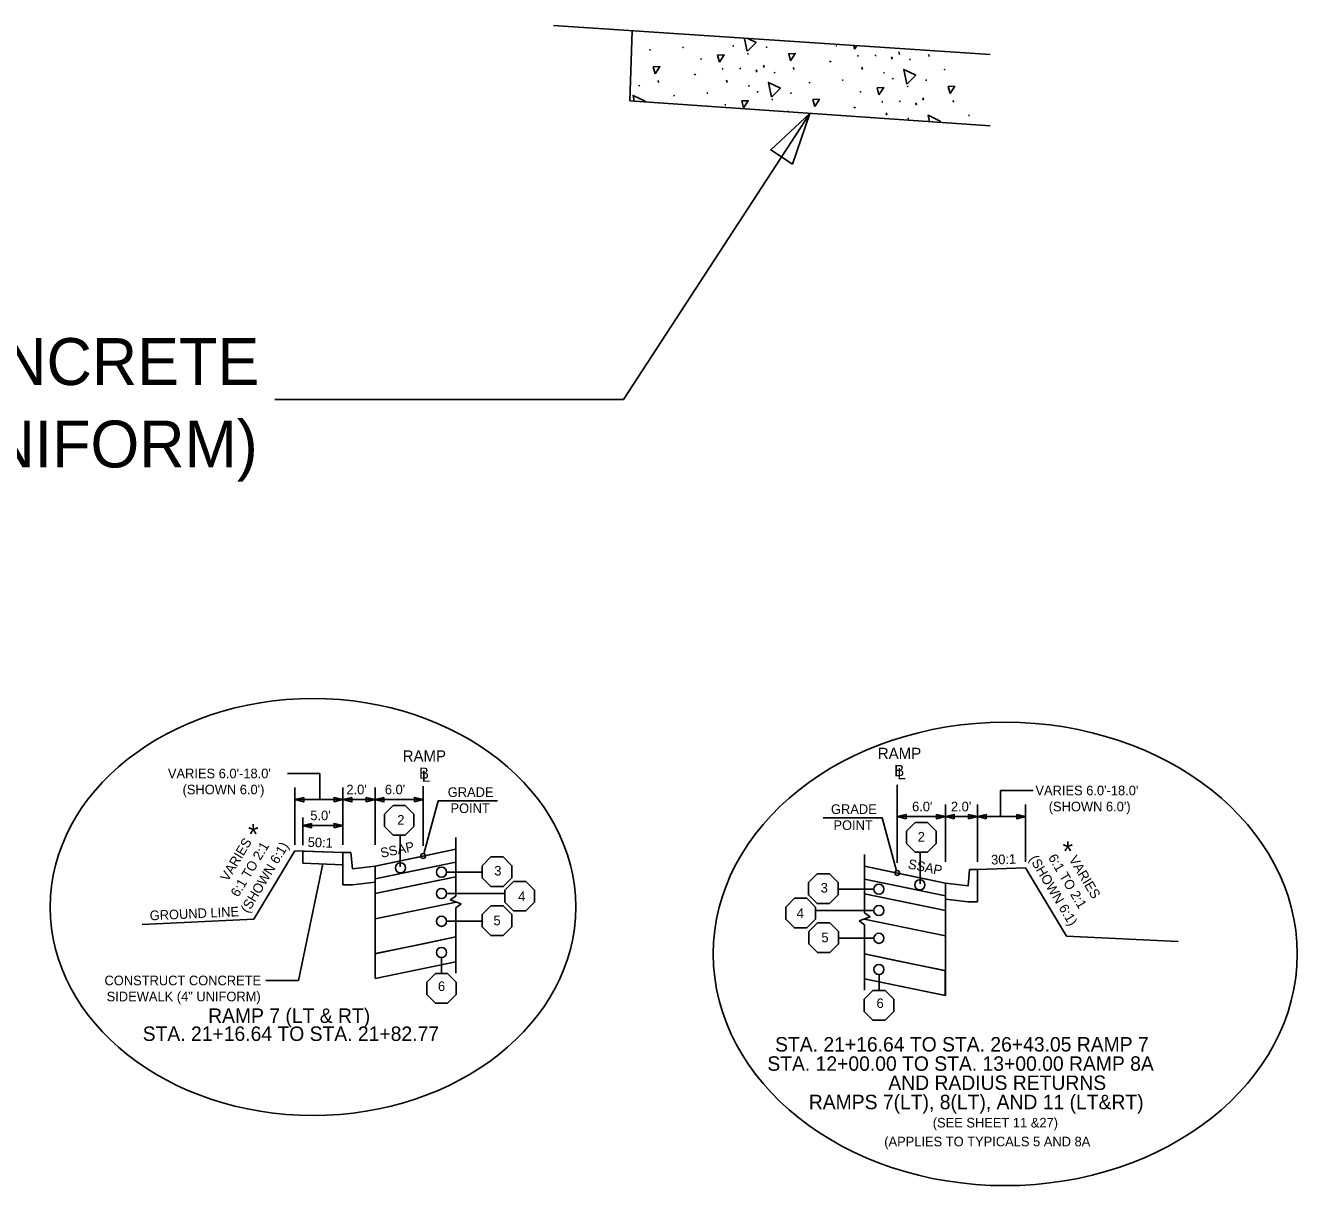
# Model space of a CAD drawing. Extents: x 4932 to 5887, y 4809 to 5473.
# Drawn here: x 5216 to 5374.1, y 5328.4 to 5473 of the extents above; entities that cross this region are included whole.
import ezdxf

# ---------------------------------------------------------------- set-up
doc = ezdxf.new("R2010")
doc.units = 0
for name, color, linetype in [('Level 1', 7, 'Continuous'), ('Level 16', 7, 'Continuous'), ('Level 25', 7, 'Continuous'), ('RD_QTY_Intermediate', 7, 'Continuous'), ('RD_QTY_Sub_Base', 7, 'Continuous'), ('RD_QTY_Surf_Course', 7, 'Continuous'), ('RD_SHT_Typical', 7, 'Continuous'), ('RD_TX_TypSect', 7, 'Continuous'), ('RD_XS_CurbBase', 7, 'Continuous'), ('RD_XS_CurbFront', 7, 'Continuous'), ('RD_XS_CurbTop', 7, 'Continuous'), ('RD_XS_EarthShd', 7, 'Continuous'), ('RD_XS_ExGround', 7, 'Continuous'), ('typical_on', 7, 'Continuous')]:
    doc.layers.add(name, color=color, linetype=linetype)

msp = doc.modelspace()

# ---------------------------------------------------------------- linework, layer by layer
at = {"layer": 'Level 1'}
for p, q in [((5291.36, 5463.6), (5291.67, 5472.36)), ((5336.27, 5460.47), (5291.36, 5463.59)), ((5290.56, 5426.39), (5313.81, 5462.03)), ((5247.12, 5426.39), (5290.56, 5426.39))]:
    msp.add_line(p, q, dxfattribs=at)
msp.add_lwpolyline([(5311.63, 5455.72), (5313.81, 5462.03), (5308.92, 5457.49)], close=True, dxfattribs=at)
at = {"layer": 'Level 16'}
for p, q in [((5324.06, 5468.78), (5323.98, 5469.09)), ((5324.96, 5469.39), (5324.87, 5469.7)), ((5328.68, 5469.15), (5328.62, 5469.37)), ((5308.09, 5467.77), (5308.01, 5468.07)), ((5311.82, 5467.53), (5311.75, 5467.74)), ((5316.24, 5468.53), (5316.46, 5468.46)), ((5320.35, 5467.51), (5320.27, 5467.81)), ((5294.95, 5465.9), (5294.89, 5466.12)), ((5299.37, 5466.91), (5299.6, 5466.83)), ((5303.48, 5465.89), (5303.4, 5466.19)), ((5307.2, 5467.16), (5307.12, 5467.46)), ((5319.27, 5462.82), (5319.49, 5462.74)), ((5327.09, 5463.07), (5327.01, 5463.37)), ((5327.98, 5463.68), (5327.9, 5463.99)), ((5331.71, 5463.44), (5331.65, 5463.65)), ((5311.08, 5462.22), (5311.04, 5462.36)), ((5314.8, 5461.96), (5314.78, 5462.03)), ((5323.38, 5461.8), (5323.29, 5462.1))]:
    msp.add_line(p, q, dxfattribs=at)
for points in [[(5305.99, 5469.78), (5305.66, 5471.34)], [(5306.09, 5471.37), (5307.1, 5470.88), (5306.02, 5469.8)], [(5293.86, 5469.91), (5293.83, 5469.96), (5293.92, 5469.95)], [(5298.01, 5470.23), (5297.98, 5470.28), (5298.07, 5470.27)], [(5302.52, 5468.43), (5302.3, 5469.3), (5303.1, 5469.34), (5302.52, 5468.43)], [(5304.25, 5470.41), (5304.22, 5470.46), (5304.32, 5470.44)], [(5306.09, 5469.43), (5306.06, 5469.48), (5306.16, 5469.47)], [(5308.41, 5470.24), (5308.38, 5470.29), (5308.48, 5470.28)], [(5311.38, 5468.61), (5311.16, 5469.48), (5311.97, 5469.52), (5311.38, 5468.61)], [(5317.11, 5470.4), (5317.08, 5470.44), (5317.18, 5470.43)], [(5319.38, 5470.05), (5319.27, 5470.5)], [(5319.61, 5470.41), (5319.38, 5470.05)], [(5319.78, 5469.16), (5319.75, 5469.21), (5319.85, 5469.2)], [(5321.98, 5469.22), (5321.95, 5469.26), (5322.05, 5469.25)], [(5291.54, 5468.67), (5291.62, 5468.66)], [(5291.55, 5468.62), (5291.54, 5468.63)], [(5294.52, 5466.99), (5294.29, 5467.86), (5295.1, 5467.9), (5294.52, 5466.99)], [(5300.24, 5468.77), (5300.21, 5468.82), (5300.31, 5468.81)], [(5302.92, 5467.54), (5302.89, 5467.59), (5302.98, 5467.58)], [(5305.12, 5467.59), (5305.09, 5467.64), (5305.19, 5467.63)], [(5325.89, 5465.69), (5325.5, 5467.52), (5327, 5466.79), (5325.91, 5465.72)], [(5326.26, 5468.7), (5326.23, 5468.75), (5326.33, 5468.74)], [(5330.61, 5467.45), (5330.58, 5467.5), (5330.68, 5467.49)], [(5309.4, 5467.08), (5309.37, 5467.12), (5309.46, 5467.11)], [(5317.9, 5466.14), (5317.87, 5466.19), (5317.97, 5466.18)], [(5323.05, 5467.06), (5323.02, 5467.11), (5323.12, 5467.1)], [(5324.14, 5466.32), (5324.11, 5466.37), (5324.21, 5466.36)], [(5328.3, 5466.16), (5328.27, 5466.2), (5328.37, 5466.19)], [(5292.53, 5465.45), (5292.5, 5465.5), (5292.6, 5465.49)], [(5301.03, 5464.52), (5301, 5464.57), (5301.1, 5464.56)], [(5306.19, 5465.44), (5306.16, 5465.49), (5306.26, 5465.47)], [(5307.28, 5464.7), (5307.25, 5464.74), (5307.35, 5464.73)], [(5309.02, 5464.07), (5308.63, 5465.9), (5310.13, 5465.17), (5309.05, 5464.09)], [(5311.44, 5464.53), (5311.41, 5464.58), (5311.51, 5464.57)], [(5313.75, 5465.83), (5313.72, 5465.87), (5313.82, 5465.86)], [(5320.13, 5464.68), (5320.1, 5464.73), (5320.2, 5464.72)], [(5322.41, 5464.34), (5322.19, 5465.21), (5323, 5465.25), (5322.41, 5464.34)], [(5325.98, 5465.34), (5325.95, 5465.39), (5326.05, 5465.38)], [(5331.28, 5464.52), (5331.05, 5465.39), (5331.86, 5465.43), (5331.28, 5464.52)], [(5291.92, 5463.55), (5291.77, 5464.27), (5293.27, 5463.55), (5293.19, 5463.46)], [(5296.88, 5464.2), (5296.85, 5464.25), (5296.95, 5464.24)], [(5303.27, 5463.06), (5303.24, 5463.11), (5303.34, 5463.1)], [(5305.54, 5462.72), (5305.33, 5463.59), (5306.13, 5463.62), (5305.54, 5462.72)], [(5309.12, 5463.72), (5309.09, 5463.77), (5309.19, 5463.76)], [(5314.41, 5462.9), (5314.18, 5463.77), (5314.99, 5463.81), (5314.41, 5462.9)], [(5322.81, 5463.45), (5322.78, 5463.5), (5322.88, 5463.49)], [(5325.01, 5463.5), (5324.98, 5463.55), (5325.08, 5463.54)], [(5326.08, 5461.35), (5326.05, 5461.4), (5326.15, 5461.39)], [(5328.7, 5461), (5328.53, 5461.81), (5330.03, 5461.08), (5329.86, 5460.92)], [(5333.64, 5461.74), (5333.61, 5461.79), (5333.71, 5461.78)]]:
    msp.add_lwpolyline(points, dxfattribs=at)
at = {"layer": 'Level 25'}
for p, q in [((5269.67, 5370.31), (5259.61, 5368.22)), ((5269.67, 5368.72), (5259.61, 5366.62)), ((5320.63, 5368.2), (5330.69, 5366.1)), ((5269.67, 5366.89), (5259.61, 5364.8)), ((5320.63, 5366.6), (5330.69, 5364.51)), ((5320.63, 5364.77), (5330.69, 5362.68))]:
    msp.add_line(p, q, dxfattribs=at)
for points in [[(5274.86, 5376.34), (5267.49, 5376.34), (5265.69, 5369.76)], [(5315.44, 5374.22), (5322.8, 5374.22), (5324.61, 5367.64)]]:
    msp.add_lwpolyline(points, dxfattribs=at)
at = {"layer": 'RD_QTY_Intermediate'}
for p, q in [((5265.61, 5367.87), (5269.67, 5368.72)), ((5269.67, 5368.72), (5269.67, 5366.89)), ((5259.61, 5366.62), (5265.61, 5367.87)), ((5259.61, 5365.36), (5259.61, 5366.62)), ((5259.61, 5364.8), (5259.61, 5366.46)), ((5259.61, 5366.46), (5259.61, 5365.36)), ((5269.67, 5366.89), (5265.61, 5366.05)), ((5320.63, 5366.6), (5320.63, 5364.77)), ((5324.69, 5365.75), (5320.63, 5366.6)), ((5265.61, 5366.05), (5259.61, 5364.8)), ((5320.63, 5364.77), (5324.69, 5363.93)), ((5330.69, 5364.51), (5324.69, 5365.75)), ((5324.69, 5363.93), (5330.69, 5362.68)), ((5330.69, 5363.24), (5330.69, 5364.51)), ((5330.69, 5362.68), (5330.69, 5364.34)), ((5330.69, 5364.34), (5330.69, 5363.24))]:
    msp.add_line(p, q, dxfattribs=at)
at = {"layer": 'RD_QTY_Sub_Base'}
for p, q in [((5259.63, 5357.3), (5265.63, 5358.54)), ((5265.63, 5358.54), (5269.67, 5359.38)), ((5269.67, 5359.38), (5269.67, 5356.28)), ((5259.63, 5354.2), (5259.63, 5357.3)), ((5320.63, 5357.26), (5320.63, 5354.16)), ((5324.66, 5356.42), (5320.63, 5357.26)), ((5269.67, 5356.28), (5259.63, 5354.2)), ((5330.67, 5355.18), (5324.66, 5356.42)), ((5320.63, 5354.16), (5330.66, 5352.09)), ((5330.66, 5352.09), (5330.67, 5355.18))]:
    msp.add_line(p, q, dxfattribs=at)
at = {"layer": 'RD_QTY_Surf_Course'}
for p, q in [((5265.61, 5369.47), (5269.67, 5370.31)), ((5269.67, 5370.31), (5269.67, 5368.72)), ((5259.61, 5368.22), (5265.61, 5369.47)), ((5259.61, 5366.62), (5259.61, 5368.22)), ((5269.67, 5368.72), (5265.61, 5367.87)), ((5324.69, 5367.35), (5320.63, 5368.2)), ((5320.63, 5368.2), (5320.63, 5366.6)), ((5265.61, 5367.87), (5259.61, 5366.62)), ((5320.63, 5366.6), (5324.69, 5365.75)), ((5330.69, 5366.1), (5324.69, 5367.35)), ((5324.69, 5365.75), (5330.69, 5364.51)), ((5330.69, 5364.51), (5330.69, 5366.1))]:
    msp.add_line(p, q, dxfattribs=at)
at = {"layer": 'RD_SHT_Typical'}
for p, q in [((5269.67, 5371.76), (5269.67, 5364.48)), ((5249.62, 5370.1), (5244.51, 5361.58)), ((5255.61, 5369.89), (5249.62, 5370.1)), ((5250.61, 5370.07), (5250.61, 5368.58)), ((5250.61, 5368.58), (5250.61, 5370.07)), ((5250.61, 5370.07), (5255.61, 5369.89)), ((5250.61, 5370.07), (5255.61, 5369.89)), ((5255.61, 5369.89), (5250.61, 5370.07)), ((5255.61, 5369.89), (5255.61, 5368.39)), ((5320.63, 5369.64), (5320.63, 5362.37)), ((5255.61, 5368.39), (5250.61, 5368.58)), ((5255.61, 5368.39), (5250.61, 5368.58)), ((5259.61, 5368.22), (5265.61, 5369.47)), ((5259.61, 5368.22), (5259.61, 5354.19)), ((5334.69, 5367.77), (5340.68, 5367.98)), ((5340.68, 5367.98), (5345.79, 5359.47)), ((5259.61, 5366.62), (5265.63, 5367.86)), ((5330.69, 5366.1), (5324.69, 5367.35)), ((5259.61, 5364.8), (5265.61, 5366.05)), ((5259.61, 5364.8), (5259.61, 5362.54)), ((5330.69, 5364.51), (5324.66, 5365.75)), ((5330.69, 5366.1), (5330.69, 5352.07)), ((5330.69, 5362.68), (5324.69, 5363.93)), ((5269.67, 5363.01), (5269.67, 5354.85)), ((5330.69, 5362.68), (5330.69, 5360.43)), ((5320.63, 5360.89), (5320.63, 5352.73))]:
    msp.add_line(p, q, dxfattribs=at)
for points in [[(5269.67, 5370.31), (5265.61, 5369.47)], [(5269.67, 5368.72), (5265.61, 5367.87)], [(5320.63, 5368.2), (5324.69, 5367.35)], [(5269.67, 5366.89), (5265.61, 5366.05)], [(5320.63, 5366.6), (5324.69, 5365.75)], [(5320.63, 5364.77), (5324.69, 5363.93)], [(5269.72, 5363.72), (5259.61, 5361.62)], [(5320.58, 5361.6), (5330.69, 5359.5)], [(5269.67, 5359.38), (5259.61, 5357.29)], [(5320.63, 5357.26), (5330.69, 5355.17)], [(5269.67, 5356.28), (5259.61, 5354.19)], [(5320.63, 5354.16), (5330.69, 5352.07)]]:
    msp.add_lwpolyline(points, dxfattribs=at)
at = {"layer": 'RD_TX_TypSect'}
for p, q in [((5248.68, 5379.77), (5252.71, 5379.77)), ((5252.71, 5379.77), (5252.71, 5376.51)), ((5249.62, 5370.87), (5249.62, 5378.03)), ((5255.61, 5370.87), (5255.61, 5378.03)), ((5259.61, 5370.87), (5259.61, 5378.03)), ((5265.61, 5378.16), (5265.61, 5370.72)), ((5324.69, 5378.33), (5324.69, 5368.6)), ((5341.62, 5377.65), (5337.58, 5377.65)), ((5337.58, 5377.65), (5337.58, 5374.39)), ((5255.61, 5376.5), (5249.62, 5376.5)), ((5259.61, 5376.5), (5255.61, 5376.5)), ((5265.61, 5376.5), (5259.61, 5376.5)), ((5330.69, 5368.75), (5330.69, 5375.91)), ((5334.68, 5368.75), (5334.68, 5375.91)), ((5340.68, 5368.75), (5340.68, 5375.91)), ((5250.61, 5370.83), (5250.61, 5374.26)), ((5324.69, 5374.38), (5330.69, 5374.38)), ((5330.69, 5374.38), (5334.68, 5374.38)), ((5334.68, 5374.38), (5340.68, 5374.38)), ((5255.61, 5373.27), (5250.61, 5373.27)), ((5262.73, 5368.12), (5262.73, 5372.07)), ((5327.56, 5366), (5327.56, 5369.95)), ((5250.05, 5353.97), (5253.11, 5368.48)), ((5268.52, 5367.46), (5272.93, 5367.46)), ((5268.52, 5364.8), (5275.8, 5364.8)), ((5321.78, 5365.34), (5317.37, 5365.34)), ((5269.67, 5364.48), (5268.98, 5364)), ((5270.34, 5363.49), (5268.98, 5364)), ((5270.34, 5363.49), (5269.67, 5363.01)), ((5321.78, 5362.68), (5314.49, 5362.68)), ((5319.95, 5361.37), (5321.31, 5361.88)), ((5320.63, 5362.37), (5321.31, 5361.88)), ((5268.52, 5361.33), (5272.93, 5361.33)), ((5319.95, 5361.37), (5320.63, 5360.89)), ((5321.78, 5359.21), (5317.37, 5359.21)), ((5267.88, 5354.82), (5267.88, 5356.82)), ((5246.01, 5353.97), (5250.05, 5353.97)), ((5322.42, 5352.7), (5322.42, 5354.7))]:
    msp.add_line(p, q, dxfattribs=at)
for points in [[(5250.72, 5376.77), (5250.72, 5376.22), (5249.62, 5376.5)], [(5254.51, 5376.22), (5254.51, 5376.77), (5255.61, 5376.5)], [(5256.72, 5376.77), (5256.72, 5376.22), (5255.61, 5376.5)], [(5258.51, 5376.22), (5258.51, 5376.77), (5259.61, 5376.5)], [(5260.71, 5376.77), (5260.71, 5376.22), (5259.61, 5376.5)], [(5264.51, 5376.22), (5264.51, 5376.77), (5265.61, 5376.5)], [(5325.79, 5374.11), (5325.79, 5374.65), (5324.69, 5374.38)], [(5329.58, 5374.65), (5329.58, 5374.11), (5330.69, 5374.38)], [(5331.79, 5374.11), (5331.79, 5374.65), (5330.69, 5374.38)], [(5333.58, 5374.65), (5333.58, 5374.11), (5334.68, 5374.38)], [(5335.79, 5374.11), (5335.79, 5374.65), (5334.68, 5374.38)], [(5339.58, 5374.65), (5339.58, 5374.11), (5340.68, 5374.38)], [(5251.71, 5373.54), (5251.71, 5372.99), (5250.61, 5373.27)], [(5254.51, 5372.99), (5254.51, 5373.54), (5255.61, 5373.27)]]:
    msp.add_lwpolyline(points, close=True, dxfattribs=at)
for centre, radius in [((5265.61, 5369.47), 0.3), ((5262.79, 5368), 0.63), ((5267.89, 5367.46), 0.63), ((5324.69, 5367.35), 0.3), ((5327.51, 5365.88), 0.63), ((5267.89, 5364.8), 0.63), ((5322.41, 5365.34), 0.63), ((5322.41, 5362.68), 0.63), ((5267.89, 5361.33), 0.63), ((5322.41, 5359.21), 0.63), ((5267.89, 5357.45), 0.63), ((5322.41, 5355.33), 0.63)]:
    msp.add_circle(centre, radius, dxfattribs=at)
for centre, major_axis in [((5251.88, 5363.11), (-32.75, 0)), ((5338.15, 5357.26), (-36.39, 0))]:
    msp.add_ellipse(centre, major_axis=major_axis, ratio=0.793631, dxfattribs=at)
at = {"layer": 'RD_XS_CurbBase'}
for p, q in [((5255.61, 5369.89), (5255.61, 5365.89)), ((5334.69, 5367.77), (5334.69, 5363.77)), ((5255.61, 5365.89), (5256.78, 5365.89)), ((5256.78, 5365.89), (5259.61, 5366.22)), ((5333.52, 5363.77), (5330.69, 5364.1)), ((5334.69, 5363.77), (5333.52, 5363.77))]:
    msp.add_line(p, q, dxfattribs=at)
at = {"layer": 'RD_XS_CurbFront'}
for p, q in [((5259.61, 5368.22), (5259.61, 5366.72)), ((5330.69, 5366.1), (5330.69, 5364.6))]:
    msp.add_line(p, q, dxfattribs=at)
at = {"layer": 'RD_XS_CurbTop'}
for p, q in [((5256.61, 5369.89), (5255.61, 5369.89)), ((5256.78, 5367.89), (5256.61, 5369.89)), ((5259.61, 5368.22), (5256.78, 5367.89)), ((5333.52, 5365.77), (5333.69, 5367.77)), ((5333.69, 5367.77), (5334.69, 5367.77)), ((5330.69, 5366.1), (5333.52, 5365.77))]:
    msp.add_line(p, q, dxfattribs=at)
at = {"layer": 'RD_XS_EarthShd'}
msp.add_line((5336.27, 5469.38), (5281.86, 5473.01), dxfattribs=at)
at = {"layer": 'RD_XS_ExGround'}
for p, q in [((5230.59, 5360.95), (5244.51, 5361.58)), ((5345.79, 5359.47), (5359.71, 5358.83))]:
    msp.add_line(p, q, dxfattribs=at)
at = {"layer": 'typical_on'}
for points in [[(5260.77, 5374.68), (5260.77, 5373.15), (5261.85, 5372.07), (5263.38, 5372.07), (5264.46, 5373.15), (5264.46, 5374.68), (5263.38, 5375.76), (5261.85, 5375.76)], [(5329.53, 5372.56), (5329.53, 5371.03), (5328.45, 5369.95), (5326.92, 5369.95), (5325.84, 5371.03), (5325.84, 5372.56), (5326.92, 5373.64), (5328.45, 5373.64)], [(5272.98, 5368.26), (5272.98, 5366.73), (5274.06, 5365.65), (5275.59, 5365.65), (5276.67, 5366.73), (5276.67, 5368.26), (5275.59, 5369.35), (5274.06, 5369.35)], [(5317.32, 5366.15), (5317.32, 5364.62), (5316.24, 5363.53), (5314.71, 5363.53), (5313.63, 5364.62), (5313.63, 5366.15), (5314.71, 5367.23), (5316.24, 5367.23)], [(5275.8, 5365.23), (5275.8, 5363.7), (5276.88, 5362.62), (5278.41, 5362.62), (5279.5, 5363.7), (5279.5, 5365.23), (5278.41, 5366.31), (5276.88, 5366.31)], [(5272.95, 5362.17), (5272.95, 5360.64), (5274.03, 5359.56), (5275.56, 5359.56), (5276.64, 5360.64), (5276.64, 5362.17), (5275.56, 5363.25), (5274.03, 5363.25)], [(5314.49, 5363.11), (5314.49, 5361.59), (5313.41, 5360.5), (5311.88, 5360.5), (5310.8, 5361.59), (5310.8, 5363.11), (5311.88, 5364.2), (5313.41, 5364.2)], [(5317.35, 5360.05), (5317.35, 5358.52), (5316.27, 5357.44), (5314.74, 5357.44), (5313.66, 5358.52), (5313.66, 5360.05), (5314.74, 5361.13), (5316.27, 5361.13)], [(5266.05, 5353.73), (5266.05, 5352.2), (5267.13, 5351.12), (5268.66, 5351.12), (5269.74, 5352.2), (5269.74, 5353.73), (5268.66, 5354.82), (5267.13, 5354.82)], [(5324.25, 5351.62), (5324.25, 5350.09), (5323.17, 5349), (5321.64, 5349), (5320.56, 5350.09), (5320.56, 5351.62), (5321.64, 5352.7), (5323.17, 5352.7)]]:
    msp.add_lwpolyline(points, close=True, dxfattribs=at)

# ---------------------------------------------------------------- texts
at = {"layer": 'Level 1'}
for s, p in [('CONSTRUCT CONCRETE ', (5150.02, 5428.18)), ('SIDEWALK (4" UNIFORM) ', (5151.4, 5417.9))]:
    msp.add_text(s, height=5.8486, rotation=0, dxfattribs=at).set_placement(p)
at = {"layer": 'Level 25'}
for s, height, p in [('RAMP', 1.4, (5263.05, 5381.24)), ('RAMP', 1.4, (5322.27, 5381.56)), ('B ', 1.4, (5324.32, 5379.42)), ('B ', 1.4, (5265.08, 5379.1)), ('GRADE', 1.2, (5268.67, 5376.83)), ('POINT', 1.2, (5269.01, 5374.83)), ('GRADE', 1.2, (5316.43, 5374.71)), ('POINT', 1.2, (5316.74, 5372.71))]:
    msp.add_text(s, height=height, dxfattribs=at).set_placement(p)
for s, rotation, p in [('50:1', 357.931, (5251.2, 5370.61)), ('SSAP', 11.7681, (5260.4, 5369.24)), ('30:1', 2.069, (5336.41, 5368.4)), ('SSAP', 348.2319, (5325.96, 5367.94))]:
    msp.add_text(s, height=1.2, rotation=rotation, dxfattribs=at).set_placement(p)
at = {"layer": 'RD_TX_TypSect'}
for s, height, p in [("VARIES 6.0'-18.0'", 1.2, (5233.79, 5379.16)), ('L', 1.4, (5265.45, 5378.72)), ('L', 1.4, (5324.71, 5379.03)), ("(SHOWN 6.0')", 1.2, (5235.62, 5377.16)), ("2.0'", 1.2, (5256.04, 5377.16)), ("6.0'", 1.2, (5260.83, 5377.16)), ("VARIES 6.0'-18.0'", 1.2, (5341.91, 5377.04)), ("6.0'", 1.2, (5326.54, 5375.04)), ("2.0'", 1.2, (5331.38, 5375.04)), ("(SHOWN 6.0')", 1.2, (5343.57, 5375.04)), ("5.0'", 1.2, (5251.54, 5373.93)), ('2', 1.2, (5262.38, 5373.38)), ('*', 2.5, (5243.78, 5370.94)), ('2', 1.2, (5327.24, 5371.27)), ('*', 2.5, (5345.3, 5368.82)), ('3', 1.2, (5274.47, 5367.03)), ('4', 1.2, (5277.45, 5363.85)), ('3', 1.2, (5315.15, 5364.91)), ('5', 1.2, (5274.37, 5360.84)), ('4', 1.2, (5312.16, 5361.73)), ('5', 1.2, (5315.24, 5358.72)), ('CONSTRUCT CONCRETE', 1.2, (5225.89, 5353.36)), ('6', 1.2, (5267.45, 5352.64)), ('SIDEWALK (4" UNIFORM)', 1.2, (5226.16, 5351.36)), ('RAMP 7 (LT & RT)', 1.8, (5238.81, 5348.67)), ('6', 1.2, (5322.11, 5350.52)), ('STA. 21+16.64 TO STA. 21+82.77', 1.8, (5230.65, 5346.42)), ('STA. 21+16.64 TO STA. 26+43.05 RAMP 7', 1.8, (5309.47, 5345.1)), ('STA. 12+00.00 TO STA. 13+00.00 RAMP 8A', 1.8, (5308.5, 5342.7)), ('AND RADIUS RETURNS', 1.8, (5323.58, 5340.31)), ('RAMPS 7(LT), 8(LT), AND 11 (LT&RT)', 1.8, (5313.67, 5337.91)), ('(SEE SHEET 11 &27)', 1.2, (5329.12, 5335.63)), ('(APPLIES TO TYPICALS 5 AND 8A ', 1.2, (5323.07, 5333.28))]:
    msp.add_text(s, height=height, dxfattribs=at).set_placement(p)
for s, rotation, p in [('VARIES', 59.0362, (5241.27, 5366.2)), ('6:1 TO 2:1', 59.0362, (5242.56, 5364.26)), ('(SHOWN 6:1)', 59.0362, (5243.81, 5362.26)), ('6:1 TO 2:1', 300.9638, (5343.45, 5369.28)), ('VARIES', 300.9638, (5346.03, 5369.07)), ('(SHOWN 6:1)', 300.9638, (5341.1, 5369.13)), ('GROUND LINE', 2.6095, (5231.55, 5361.45))]:
    msp.add_text(s, height=1.2, rotation=rotation, dxfattribs=at).set_placement(p)

doc.saveas('drawing.dxf')
